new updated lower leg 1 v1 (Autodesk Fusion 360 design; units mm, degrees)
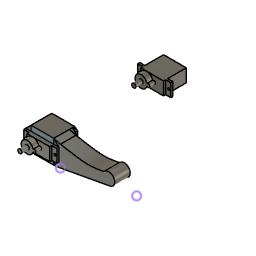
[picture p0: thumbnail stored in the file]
derived_base_feature "衍生的基础特征"
delete_face "DeleteFace1"
sketch "Sketch1" plane through (0, 0, 0.2137) normal (0, 0, 1) x axis (-1, 0, 0)
  line L1 (0, -1.2901) -> (0, -19.2901)
  line L2 (5, -1.2901) -> (0, -1.2901)
  line L3 (5, 0.7099) -> (5, -1.2901)
  line L4 (0, 0.7099) -> (5, 0.7099)
  line L5 (0, 2.7099) -> (0, 0.7099)
  line L6 (-5.75, 2.7099) -> (0, 2.7099)
  line L7 (-22, 2.7099) -> (-5.75, 2.7099)
  line L8 (-22, 0.7099) -> (-22, 2.7099)
  line L9 (-27, 0.7099) -> (-22, 0.7099)
  line L10 (-27, -1.2901) -> (-27, 0.7099)
  line L11 (-22, -1.2901) -> (-27, -1.2901)
  line L12 (-22, -19.2901) -> (-22, -1.2901)
  line L13 (0, -19.2901) -> (-22, -19.2901)
sketch "Sketch2" plane through (0, 0, 0.2137) normal (0, 0, 1) x axis (-1, 0, 0)
  line L1 (0, -1.29) -> (-22, -1.29)
  line L2 (0, -19.3) -> (0, -1.29)
  line L3 (-22, -19.3) -> (0, -19.3)
  line L4 (-22, -1.29) -> (-22, -19.3)
  horizontal L1
  vertical L2
  horizontal L3
  vertical L4
extrude "Extrude1" new body sketch "Sketch2" along normal blind 5
extrude "Extrude1" new body of existing geometry blind 5
sketch "Sketch3" plane through (0, 0, 0) normal (-1, 0, 0) x axis (0, -1, 0)
  line L1 (-1.2901, 0.2137) -> (-1.2901, -12.2863)
  line L2 (-19.2901, 0.2137) -> (-1.2901, 0.2137)
  line L3 (-19.2901, -12.2863) -> (-19.2901, 0.2137)
  line L4 (-1.2901, -12.2863) -> (-19.2901, -12.2863)
  line L5 (-12.4561, -12.2863) -> (-1.2901, -12.2863)
  line L6 (-12.4561, 0.2137) -> (-12.4561, -12.2863)
  line L7 (-1.2901, 0.2137) -> (-12.4561, 0.2137)
  line L8 (-1.2901, -12.2863) -> (-1.2901, 0.2137)
  point P8 (-12.4561, 0.2137)
  point P2 (-1.2901, -12.2863)
  point P6 (-1.2901, -12.2863)
  horizontal L5
  vertical L6
  horizontal L7
  vertical L8
  coincident L2 P8
  coincident P2 P6
extrude "Extrude2" new body sketch "Sketch3" profile of L1 L2 L4 L5 L6 L7 L8 along normal blind 5
sketch "Sketch4" plane through (0, 0, -12.2863) normal (0, 0, -1) x axis (1, 0, 0)
  line L1 (0, -19.2901) -> (0, -1.2901)
  line L2 (22, -19.2901) -> (0, -19.2901)
  line L3 (22, -1.2901) -> (22, -19.2901)
  line L4 (27, -1.2901) -> (22, -1.2901)
  line L5 (27, 0.7099) -> (27, -1.2901)
  line L6 (22, 0.7099) -> (27, 0.7099)
  line L7 (22, 2.7099) -> (22, 0.7099)
  line L8 (0, 2.7099) -> (22, 2.7099)
  line L9 (0, 0.7099) -> (0, 2.7099)
  line L10 (-5, 0.7099) -> (0, 0.7099)
  line L11 (-5, -1.2901) -> (-5, 0.7099)
  line L12 (0, -1.2901) -> (-5, -1.2901)
  line L13 (0.0405, -19.2901) -> (22, -19.2901)
  line L14 (0.0405, -1.3176) -> (0.0405, -19.2901)
  line L15 (22, -1.3176) -> (0.0405, -1.3176)
  line L16 (22, -19.2901) -> (22, -1.3176)
  point P4 (22, -19.2901)
  point P14 (22, -19.2901)
  horizontal L13
  vertical L14
  horizontal L15
  vertical L16
  coincident P4 P14
extrude "Extrude3" new body sketch "Sketch4" profile of L2 L3 L13 L14 L15 L16 along normal blind 5
loft "Loft1"
loft "Loft2"
sketch "Sketch5" plane through (0, 19.2901, 0) normal (0, 1, 0) x axis (-1, 0, 0)
  line L1 (0, 0.2137) -> (0, -12.2863)
  line L2 (-22, 0.2137) -> (0, 0.2137)
  line L3 (-22, -12.2863) -> (-22, 0.2137)
  line L4 (0, -12.2863) -> (-22, -12.2863)
  line L5 (-10, -12.2863) -> (-22, -12.2863)
  line L6 (-10, 0) -> (-10, -12.2863)
  line L7 (-22, 0) -> (-10, 0)
  line L8 (-22, -12.2863) -> (-22, 0)
  point P5 (-22, -12.2863)
  point P6 (-22, -12.2863)
  horizontal L5
  vertical L6
  horizontal L7
  vertical L8
  coincident P5 P6
extrude "Extrude4" new body sketch "Sketch5" profile of L3 L4 L5 L6 L7 L8 along normal blind 5
sketch "Sketch6" plane through (0, 19.2901, 0) normal (0, 1, 0) x axis (-1, 0, 0)
  line L1 (-22, 0.2137) -> (-22, -12.2863)
  line L2 (-27, 0.2137) -> (-22, 0.2137)
  line L3 (-27, -12.2863) -> (-27, 0.2137)
  line L4 (-22, -17.2863) -> (-27, -12.2863)
  line L5 (-0.0405, -17.2863) -> (-22, -17.2863)
  line L6 (-0.0405, -12.2863) -> (-0.0405, -17.2863)
  line L7 (-22, -12.2863) -> (-0.0405, -12.2863)
  line L8 (-22.0573, -17.2863) -> (-10.0644, -17.2863)
  line L9 (-22.0573, -12.2863) -> (-22.0573, -17.2863)
  line L10 (-10.0644, -12.2863) -> (-22.0573, -12.2863)
  line L11 (-10.0644, -17.2863) -> (-10.0644, -12.2863)
  point P9 (-10.0644, -17.2863)
  horizontal L8
  vertical L9
  horizontal L10
  vertical L11
  coincident L5 P9
extrude "Extrude5" new body sketch "Sketch6" profile of L4 L5 L7 L8 L9 L10 L11 along normal blind 5
sketch "Sketch7" plane through (0, 19.3, 0) normal (0, 1, 0) x axis (-1, 0, 0)
  line L1 (0, 0.2137) -> (-22, 0.2137)
  line L2 (0, 5.2137) -> (0, 0.2137)
  line L3 (-22, 5.2137) -> (0, 5.2137)
  line L4 (-22, 0.2137) -> (-22, 5.2137)
  line L5 (-22, 0.2137) -> (-10.0149, 0.2137)
  line L6 (-22, 5.2137) -> (-22, 0.2137)
  line L7 (-10.0149, 5.2137) -> (-22, 5.2137)
  line L8 (-10.0149, 0.2137) -> (-10.0149, 5.2137)
  point P5 (-22, 5.2137)
  point P8 (-22, 5.2137)
  point P6 (-10.0149, 0.2137)
  horizontal L5
  vertical L6
  horizontal L7
  vertical L8
  coincident P5 P8
  coincident L1 P6
extrude "Extrude6" cut of existing geometry blind -3
extrude "Extrude2" add sketch "Sketch7" profile of L1 L3 L4 L5 L6 L7 L8 along normal blind 2
loft "Loft3"
loft "Loft1"
loft "Loft4"
sketch "Sketch8" plane through (-5, 0, 0) normal (-1, 0, 0) x axis (0, -1, 0)
  line L1 (-12.4561, 0.2137) -> (-1.2901, 0.2137)
  line L2 (-12.4561, -12.2863) -> (-12.4561, 0.2137)
  line L3 (-1.2901, -12.2863) -> (-12.4561, -12.2863)
  line L4 (-1.2901, 0.2137) -> (-1.2901, -12.2863)
sketch "Sketch9" plane through (0, 0, 0) normal (-1, 0, 0) x axis (0, -1, 0)
  line L1 (-1.29, 0.2137) -> (-19.3, 0.2137)
  line L2 (-1.29, 5.2137) -> (-1.29, 0.2137)
  line L3 (-19.3, 5.2137) -> (-1.29, 5.2137)
  line L4 (-19.3, 0.2137) -> (-19.3, 5.2137)
  line L5 (-12.4168, 0.2137) -> (-1.29, 0.2137)
  line L6 (-12.4168, 5.2137) -> (-12.4168, 0.2137)
  line L7 (-1.29, 5.2137) -> (-12.4168, 5.2137)
  line L8 (-1.29, 0.2137) -> (-1.29, 5.2137)
  point P8 (-12.4168, 5.2137)
  point P3 (-1.29, 0.2137)
  point P6 (-1.29, 0.2137)
  horizontal L5
  vertical L6
  horizontal L7
  vertical L8
  coincident L3 P8
  coincident P3 P6
loft "Loft5" sketch "Sketch9"
sketch "Sketch10" plane through (0.0405, 0, 0) normal (-1, 0, 0) x axis (0, -1, 0)
  line L1 (-19.2901, -12.2863) -> (-1.3176, -12.2863)
  line L2 (-19.2901, -17.2863) -> (-19.2901, -12.2863)
  line L3 (-1.3176, -17.2863) -> (-19.2901, -17.2863)
  line L4 (-1.3176, -12.2863) -> (-1.3176, -17.2863)
  line L5 (-12.3877, -17.2863) -> (-1.3176, -17.2863)
  line L6 (-12.3877, -12.2863) -> (-12.3877, -17.2863)
  line L7 (-1.3176, -12.2863) -> (-12.3877, -12.2863)
  line L8 (-1.3176, -17.2863) -> (-1.3176, -12.2863)
  point P8 (-12.3877, -12.2863)
  point P5 (-1.3176, -17.2863)
  point P6 (-1.3176, -17.2863)
  horizontal L5
  vertical L6
  horizontal L7
  vertical L8
  coincident L1 P8
  coincident P5 P6
loft "Loft6" sketch "Sketch10"
sketch "Sketch11" plane through (0, 12.4561, 0) normal (0, 1, 0) x axis (-1, 0, 0)
  line L1 (0, -12.2863) -> (0, 0.2137)
  line L2 (5, -12.2863) -> (0, -12.2863)
  line L3 (5, 0.2137) -> (5, -12.2863)
  line L4 (0, 0.2137) -> (5, 0.2137)
  line L5 (2.2932, -5.3234) -> (0.5323, -5.3234)
  line L6 (2.2932, -7.6985) -> (2.2932, -5.3234)
  line L7 (0.5323, -7.6985) -> (2.2932, -7.6985)
  line L8 (0.5323, -5.3234) -> (0.5323, -7.6985)
  horizontal L5
  vertical L6
  horizontal L7
  vertical L8
extrude "Extrude7" cut sketch "Sketch11" profile of L5 L6 L7 L8 against normal blind 11.1
sketch "Sketch12" plane through (0, 0, 5.2137) normal (0, 0, 1) x axis (-1, 0, 0)
  line L1 (0, -19.3) -> (-10.0149, -19.3)
  line L2 (0, -1.29) -> (0, -19.3)
  line L3 (-22, -1.29) -> (0, -1.29)
  line L4 (-22, -21.3) -> (-22, -1.29)
  line L5 (-10.0149, -21.3) -> (-22, -21.3)
  line L6 (-10.0149, -19.3) -> (-10.0149, -21.3)
combine "Combine1"
sketch "Sketch13" plane through (0, 1.3176, 0) normal (0, -1, 0) x axis (1, 0, 0)
  line L1 (0.0405, -12.2863) -> (22, -12.2863)
  line L2 (0.0405, -17.2863) -> (0.0405, -12.2863)
  line L3 (22, -17.2863) -> (0.0405, -17.2863)
  line L4 (22, -12.2863) -> (22, -17.2863)
  curve K1 (92.1405, 7.26) -> (22, 5.2125)
  curve K2 (103.3069, -2.4795) -> (22, -17.2863)
  line L5 (22, -17.2863) -> (22, 5.2125)
  circle C1 centre (100, 5) radius 8.1779
  point P10 (92.1405, 7.26)
  point P5 (22, -17.2863)
  point P11 (22, -17.2863)
  point P15 (103.3069, -2.4795)
  point P16 (22, -17.2863)
  coincident C1 P10
  coincident P5 P11
  coincident C1 P15
  coincident P5 P16
extrude "Extrude3" add sketch "Sketch13" profile of L4 C1 K1 K2 L5 against normal blind 15
extrude "Extrude4" cut of existing geometry blind -0.532
sketch "Sketch14" plane through (0, 19.2901, 0) normal (0, 1, 0) x axis (-1, 0, 0)
  line L1 (0, 0.2137) -> (0, -12.2863)
  line L2 (-22, 0.2137) -> (0, 0.2137)
  line L3 (-22, -12.2863) -> (-22, 0.2137)
  line L4 (0, -12.2863) -> (-22, -12.2863)
  line L5 (-9.5989, 0.2137) -> (0, 0.2137)
  line L6 (-9.5989, -12.2863) -> (-9.5989, 0.2137)
  line L7 (0, -12.2863) -> (-9.5989, -12.2863)
  line L8 (0, 0.2137) -> (0, -12.2863)
  point P8 (-9.5989, -12.2863)
  point P3 (0, 0.2137)
  point P6 (0, 0.2137)
  horizontal L5
  vertical L6
  horizontal L7
  vertical L8
  coincident L4 P8
  coincident P3 P6
extrude "Extrude8" new body sketch "Sketch14" profile of L1 L2 L4 L5 L6 L7 L8 along normal blind 5
extrude "Extrude5" add of existing geometry blind 2
extrude "Extrude6" add of existing geometry blind 2
loft "Loft2"
loft "Loft3"
loft "Loft7"
sketch "Sketch15" plane through (0, -15.2099, 0) normal (0, -1, 0) x axis (1, 0, 0)
  circle C1 centre (5.75, -5.5363) radius 2
sketch "Sketch16" plane through (0, 24.2901, 0) normal (0, 1, 0) x axis (-1, 0, 0)
  line L1 (0, 0.2137) -> (0, -12.2863)
  line L2 (-9.5989, 0.2137) -> (0, 0.2137)
  line L3 (-9.5989, -12.2863) -> (-9.5989, 0.2137)
  line L4 (0, -12.2863) -> (-9.5989, -12.2863)
sketch "Sketch17" plane through (0, -15.2099, 0) normal (0, -1, 0) x axis (1, 0, 0)
sketch "Sketch18" plane through (0, 24.2901, 0) normal (0, 1, 0) x axis (-1, 0, 0)
  circle C1 centre (-5.7487, -5.457) radius 2.15
  dimension "d29" diameter C1 = 4.3
extrude "Extrude9" add sketch "Sketch18" along normal blind 4.4
move "Move1"
position "Position1"
extrude "Extrude7" cut of existing geometry blind -3
combine "Combine2"
extrude "Extrude8" cut of existing geometry blind -1
extrude "Extrude9" cut of existing geometry blind -1
extrude "Extrude10" cut of existing geometry blind -1
extrude "Extrude11" cut of existing geometry blind -1
extrude "Extrude12" add of existing geometry blind 0.25
extrude "Extrude13" add of existing geometry blind 0.25
extrude "Extrude14" add of existing geometry blind 0.3
extrude "Extrude15" cut of existing geometry blind -0.5
extrude "Extrude16" cut of existing geometry blind -0.1
extrude "Extrude17" cut of existing geometry blind -0.28
move "Move1"
position "Position2"
extrude "Extrude18" add of existing geometry blind 1
position "Position3"
sketch "Sketch19" plane through (0, 41.2901, 0) normal (0, -1, 0) x axis (1, 0, 0)
  line L1 (0, 0.2137) -> (0, -4.5734)
  line L2 (-5, 0.2137) -> (0, 0.2137)
  line L3 (-5, -12.2863) -> (-5, 0.2137)
  line L4 (0, -12.2863) -> (-5, -12.2863)
  line L5 (0, -8.4485) -> (0, -12.2863)
  line L6 (-1.9932, -8.4485) -> (0, -8.4485)
  line L7 (-1.9932, -4.5734) -> (-1.9932, -8.4485)
  line L8 (0, -4.5734) -> (-1.9932, -4.5734)
sketch "Sketch20" plane through (0, 41.2901, 0) normal (0, -1, 0) x axis (1, 0, 0)
  line L1 (0, 0.2137) -> (0, -4.5734)
  line L2 (-5, 0.2137) -> (0, 0.2137)
  line L3 (-5, -12.2863) -> (-5, 0.2137)
  line L4 (0, -12.2863) -> (-5, -12.2863)
  line L5 (0, -8.4485) -> (0, -12.2863)
  line L6 (-1.9932, -8.4485) -> (0, -8.4485)
  line L7 (-1.9932, -4.5734) -> (-1.9932, -8.4485)
  line L8 (0, -4.5734) -> (-1.9932, -4.5734)
  circle C1 centre (-3, -6) radius 0.815
  dimension "d56" diameter C1 = 1.63
sketch "Sketch21" plane through (0, 41.2901, 0) normal (0, -1, 0) x axis (1, 0, 0)
  line L1 (22.5, -12.2863) -> (22.5, 0.2137)
  line L2 (27, -12.2863) -> (22.5, -12.2863)
  line L3 (27, 0.2137) -> (27, -12.2863)
  line L4 (22.5, 0.2137) -> (27, 0.2137)
  circle C1 centre (25, -6) radius 0.815
  dimension "d57" diameter C1 = 1.63
sketch "Sketch22" plane through (0, 41.2901, 0) normal (0, -1, 0) x axis (1, 0, 0)
  line L1 (0, 0.2137) -> (0, -4.5734)
  line L2 (-5, 0.2137) -> (0, 0.2137)
  line L3 (-5, -12.2863) -> (-5, 0.2137)
  line L4 (0, -12.2863) -> (-5, -12.2863)
  line L5 (0, -8.4485) -> (0, -12.2863)
  line L6 (-1.9932, -8.4485) -> (0, -8.4485)
  line L7 (-1.9932, -4.5734) -> (-1.9932, -8.4485)
  line L8 (0, -4.5734) -> (-1.9932, -4.5734)
extrude "Extrude19" cut sketch "Sketch20" profile of C1 against normal blind 3
sketch "Sketch23" plane through (0, 41.3176, 0) normal (0, -1, 0) x axis (1, 0, 0)
  line L1 (27, 0.2137) -> (22.0018, 5.212)
  line L2 (27, -12.2863) -> (27, 0.2137)
  line L3 (22, -17.2863) -> (27, -12.2863)
  curve K1 (102.0404, -2.9193) -> (22, -17.2863)
  curve K2 (103.3069, -2.4795) -> (102.0404, -2.9193)
  curve K3 (92.1405, 7.26) -> (22.0018, 5.212)
  arc A1 centre (100, 5) radius 8.1779 clockwise from (92.1405, 7.26) to (103.3069, -2.4795)
sketch "Sketch24" plane through (0, 39.2901, 0) normal (0, -1, 0) x axis (1, 0, 0)
  line L1 (22, -12.2863) -> (22, 0.2137)
  line L2 (27, -12.2863) -> (22, -12.2863)
  line L3 (27, 0.2137) -> (27, -12.2863)
  line L4 (22, 0.2137) -> (27, 0.2137)
  circle C1 centre (25, -6.0363) radius 1
  circle C2 centre (25, -6.0363) radius 0.815
  concentric C1 C2
  dimension "d60" diameter C2 = 1.63
extrude "Extrude20" cut sketch "Sketch24" profile of C2 against normal blind 2.1
position "Position4"
extrude "Extrude21" cut of existing geometry blind -2.9
thread "Thread1" ThreadOffset 0 ThreadLength 10
thread "Thread2" ThreadOffset 0 ThreadLength 10
loft "Loft4"
loft "Loft5"
position "Position5"
extrude "Extrude22" add of existing geometry blind 0.1
copy_paste "CopyPaste1"
work_plane "WorkPlane1"
sketch "Sketch1" plane through (0, 56.3176, 0) normal (0, 1, 0) x axis (-1, 0, 0)
  line L1 (-22.0018, 5.212) -> (-27, 0.2137)
  curve K1 (-92.1405, 7.26) -> (-22.0018, 5.212)
  curve K2 (-102.0404, -2.9193) -> (-103.3069, -2.4795)
  curve K3 (-22, -17.2863) -> (-102.0404, -2.9193)
  line L2 (-27, -12.2863) -> (-22, -17.2863)
  line L3 (-27, 0.2137) -> (-27, -12.2863)
  line L4 (-28.3506, -16.4558) -> (-28.3506, 3.4751)
  arc A1 centre (-100, 5) radius 8.1779 clockwise from (-103.3069, -2.4795) to (-92.1405, 7.26)
  point P10 (-28.3506, 3.4751)
  point P11 (-28.3506, -16.4558)
  coincident K1 P10
  coincident K3 P11
  vertical L4
split "Split1"
sketch "Sketch2" plane through (0, 41.3176, 0) normal (0, -1, 0) x axis (1, 0, 0)
  line L1 (28.3506, -16.4558) -> (28.3506, 3.4751)
  curve K1 (103.3069, -2.4795) -> (102.0404, -2.9193)
  curve K2 (92.1405, 7.26) -> (28.3506, 3.4751)
  arc A1 centre (100, 5) radius 8.1779 clockwise from (92.1405, 7.26) to (103.3069, -2.4795)
remove_body "RemoveBody1"
sketch "Sketch3" plane through (0, 41.29, 0) normal (0, -1, 0) x axis (1, 0, 0)
  line L1 (22, 0.2137) -> (0, 0.2137)
  line L2 (22, 5.2137) -> (22, 0.2137)
  line L3 (0, 5.2137) -> (22, 5.2137)
  line L4 (0, 0.2137) -> (0, 5.2137)
sketch "Sketch4" plane through (0, 41.3176, 0) normal (0, -1, 0) x axis (1, 0, 0)
  line L1 (28.3506, 3.4751) -> (28.3506, -16.4558)
  curve K1 (28.3506, 3.4751) -> (22.0018, 5.212)
  line L2 (27, 0.2137) -> (22.0018, 5.212)
  line L3 (27, -12.2863) -> (27, 0.2137)
  line L4 (22, -17.2863) -> (27, -12.2863)
  curve K2 (28.3506, -16.4558) -> (22, -17.2863)
sketch "Sketch5" plane through (0, 41.3176, 0) normal (0, -1, 0) x axis (1, 0, 0)
  circle C1 centre (75, -2) radius 5.831
sketch "Sketch7" plane through (0, 41.3176, 0) normal (0, -1, 0) x axis (1, 0, 0)
  curve K1 (70.49, 1.69) -> (28.35, 3.475)
  curve K2 (75, -7.83) -> (28.35, -16.455)
  line L1 (70.49, 1.69) -> (75, -7.83)
  line L2 (28.35, 3.475) -> (28.35, -16.455)
  vertical L2
extrude "Extrude23" add sketch "Sketch5" + "Sketch7" blind -15
sketch "Sketch6" plane through (0, 41.3176, 0) normal (0, -1, 0) x axis (1, 0, 0)
  line L1 (28.2889, 3.3751) -> (28.3277, -16.4387)
  line L2 (28.285, 3.3699) -> (28.2889, 3.3751)
  line L3 (70, 1) -> (75.5, -7.8)
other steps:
create_component "CreateComponent1"
create_component "CreateComponent2"
remove_body "RemoveBody1"
remove_body "RemoveBody2"
create_component "CreateComponent1"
